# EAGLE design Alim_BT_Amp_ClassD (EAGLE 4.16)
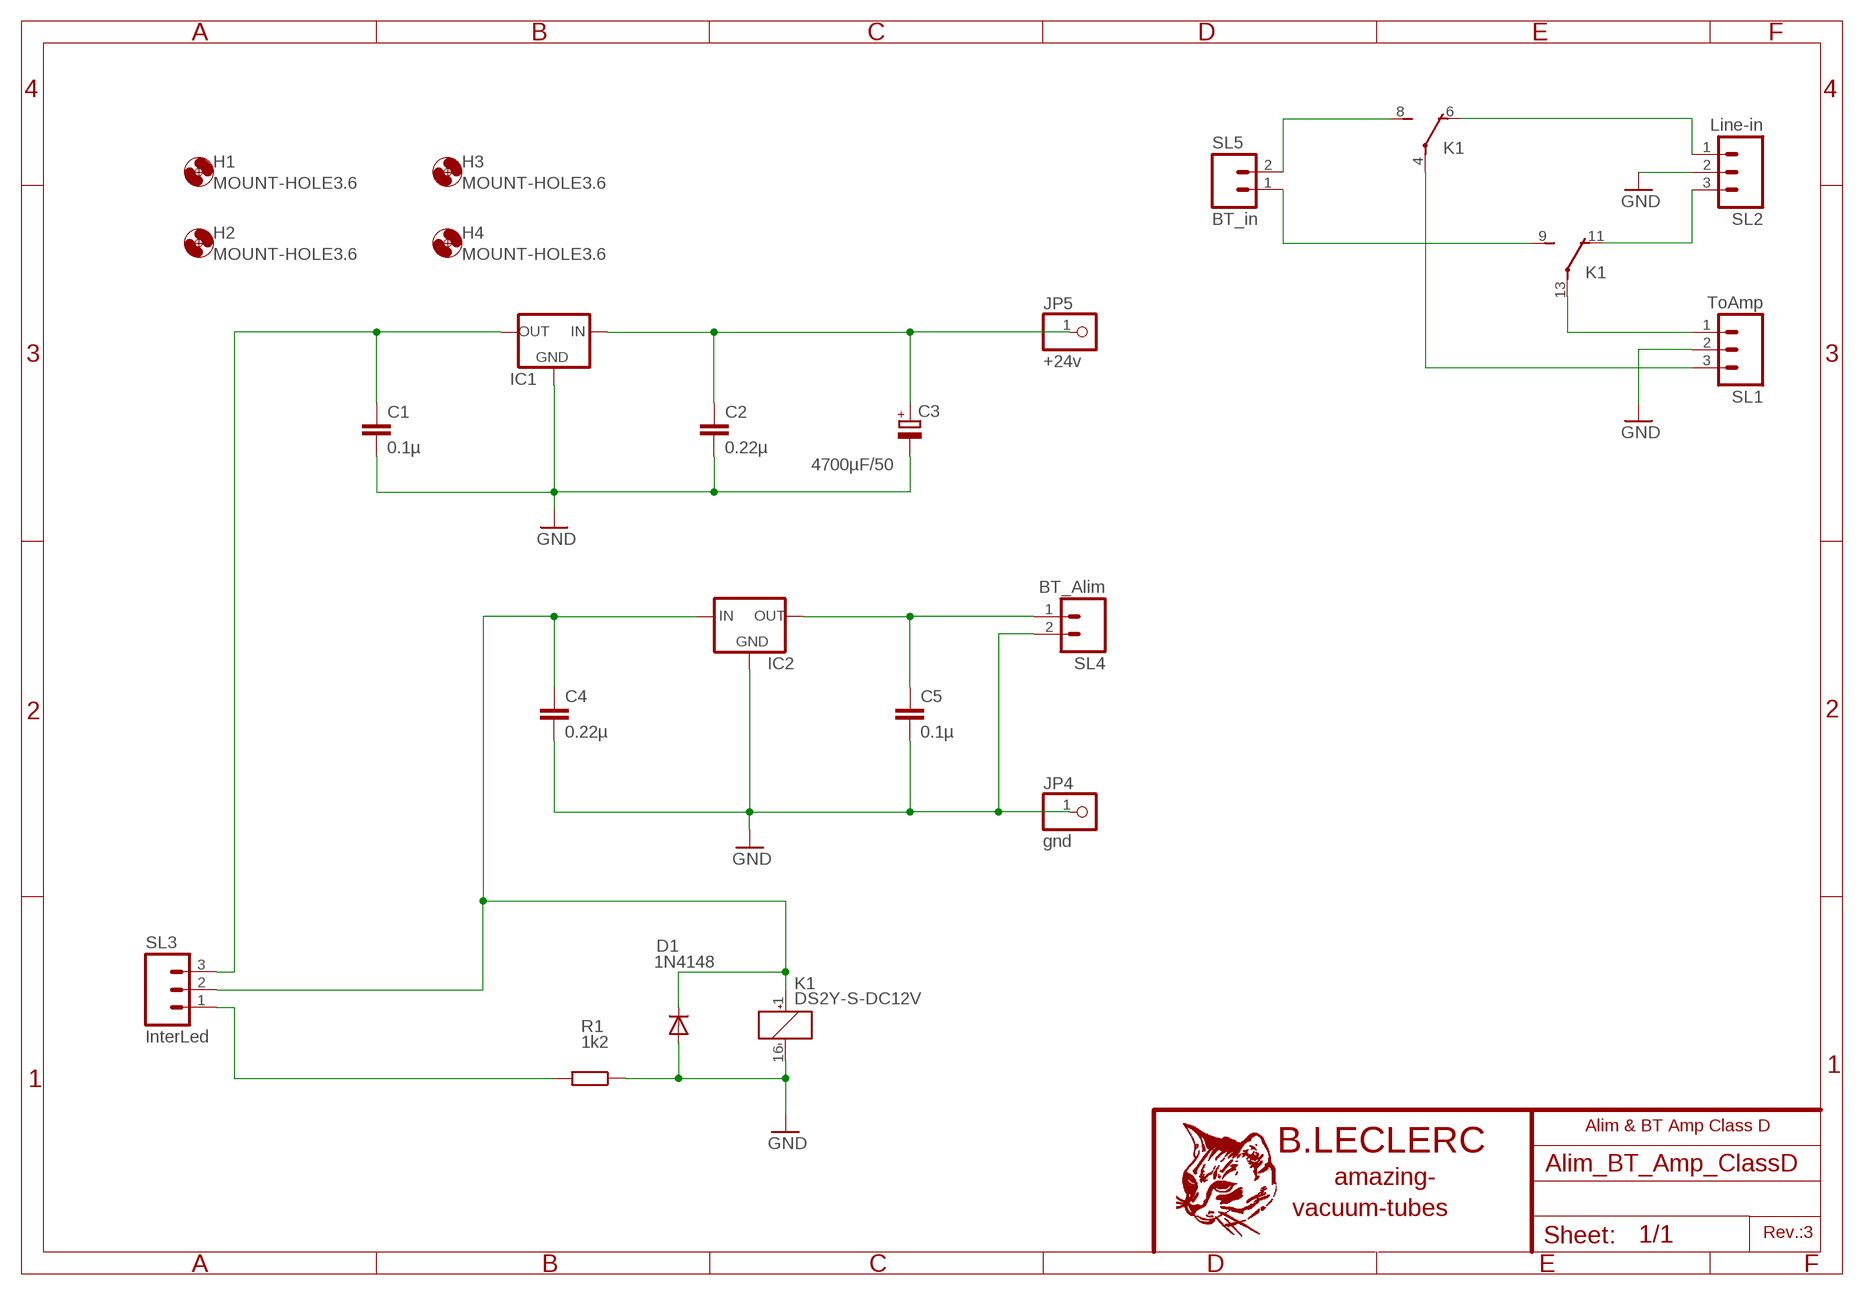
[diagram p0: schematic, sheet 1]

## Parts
C1  0.1µ  C-EU102-064X133  [C102-064X133]
C2  0.22µ  C-EU102-064X133  [C102-064X133]
C3  4700µF/50  CPOL-EUE7.5-18  [E7,5-18]
C4  0.22µ  C-EU102-064X133  [C102-064X133]
C5  0.1µ  C-EU102-064X133  [C102-064X133]
D1  1N4148  [DO35-10]
H1  MOUNT-HOLE3.6  [3,6]
H2  MOUNT-HOLE3.6  [3,6]
H3  MOUNT-HOLE3.6  [3,6]
H4  MOUNT-HOLE3.6  [3,6]
IC1  78XXL  [78XXL]
IC2  78XXL  [78XXL]
JP4  gnd  PINHD-1X1  [1X01]
JP5  +24v  PINHD-1X1  [1X01]
K1  DS2Y-S-DC12V  DS2Y-S-DC24V  [DS2Y]
R1  1k2  R-EU_0207/12  [0207/12]
SL1  ToAmp  M03  [03P]
SL2  Line-in  M03  [03P]
SL3  InterLed  M03  [03P]
SL4  BT_Alim  M02  [02P]
SL5  BT_in  M02  [02P]

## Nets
GND: C1.2 C2.2 C3.- C4.2 C5.2 D1.A IC1.GND IC2.GND JP4.1 K1.16(1:-) R1.1 SL1.2 SL2.2 SL4.2
N$1: K1.4(2:P) SL1.3
N$2: R1.2 SL3.1
N$4: C4.1 D1.C IC2.IN K1.1(1:+) SL3.2
N$5: K1.8(2:S) SL5.2
N$6: C5.1 IC2.OUT SL4.1
N$7: K1.6(2:O) SL2.1
N$8: C1.1 IC1.OUT SL3.3
N$9: K1.9(3:S) SL5.1
N$10: K1.11(3:O) SL2.3
N$11: K1.13(3:P) SL1.1
N$13: C2.1 C3.+ IC1.IN JP5.1

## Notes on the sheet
- Alim & BT Amp Class D
- Rev.:3

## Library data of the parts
C1 C2 C4 C5 = rcl:C-EU: CAPACITOR, European symbol
C3 = rcl:CPOL-EU: POLARIZED CAPACITOR, European symbol
D1 = diode:1N4148: DIODE
H1-H4 = holes:MOUNT-HOLE: MOUNTING HOLE with drill center marker
IC1 IC2 = v-reg:78XXL: VOLTAGE REGULATOR
JP4 JP5 = pinhead:PINHD-1X1: PIN HEADER
K1 = relay:DS2Y-S-DC*: MINIATURE RELAY NAiS Source: http://www.mew-europe.com/.. en_ds_61005_0023.pdf
R1 = rcl:R-EU_: RESISTOR, European symbol
SL1-SL3 = con-amp-quick:M03: AMP QUICK CONNECTOR
SL4 SL5 = con-amp-quick:M02: AMP QUICK CONNECTOR

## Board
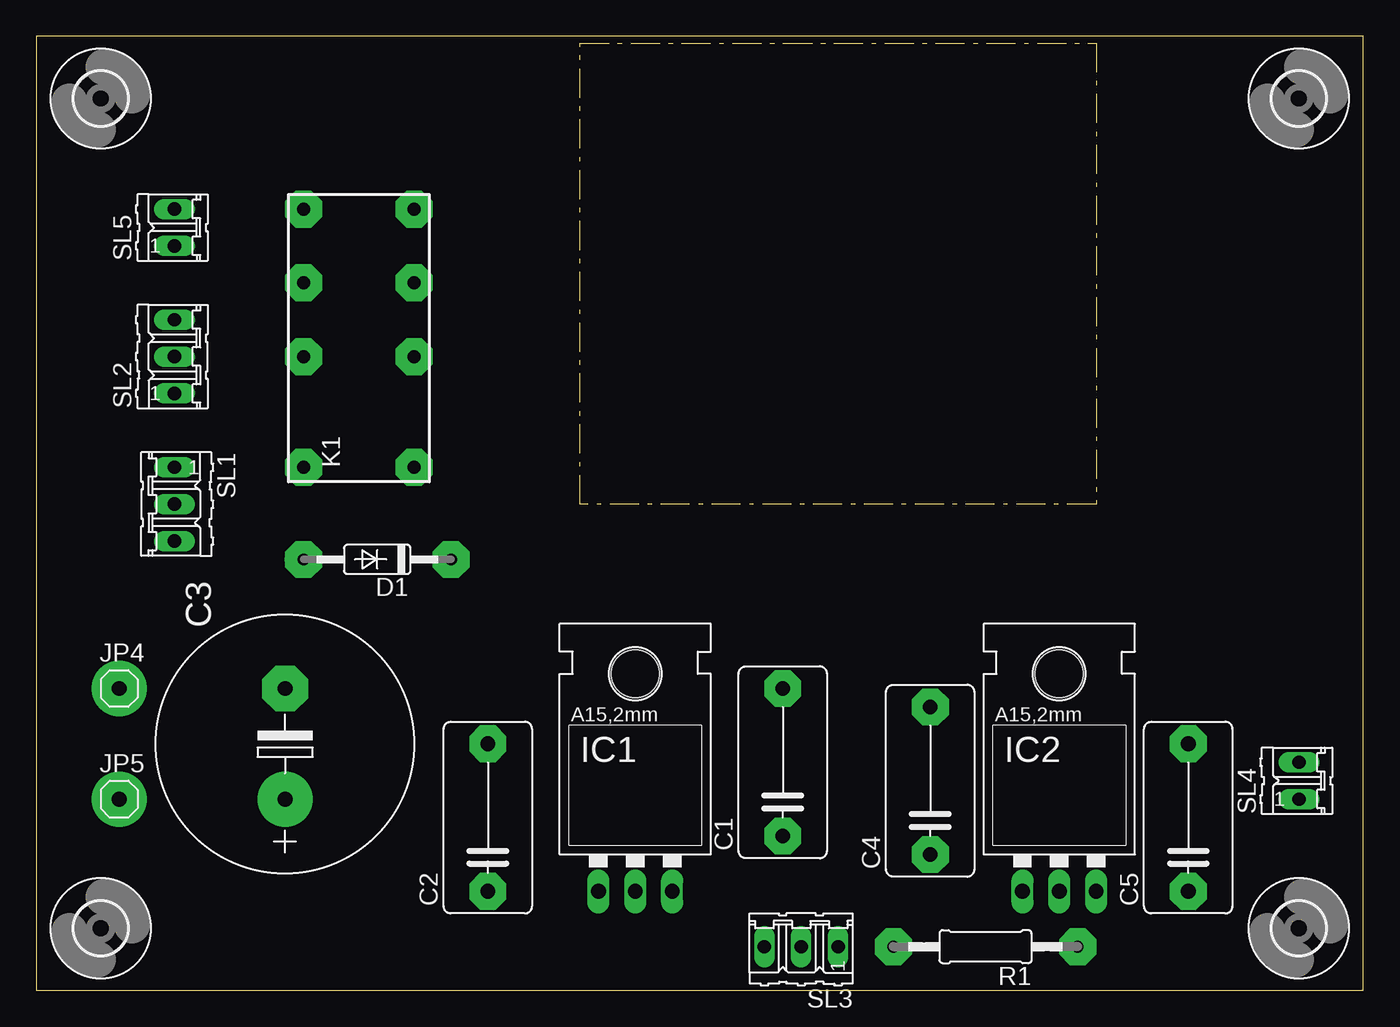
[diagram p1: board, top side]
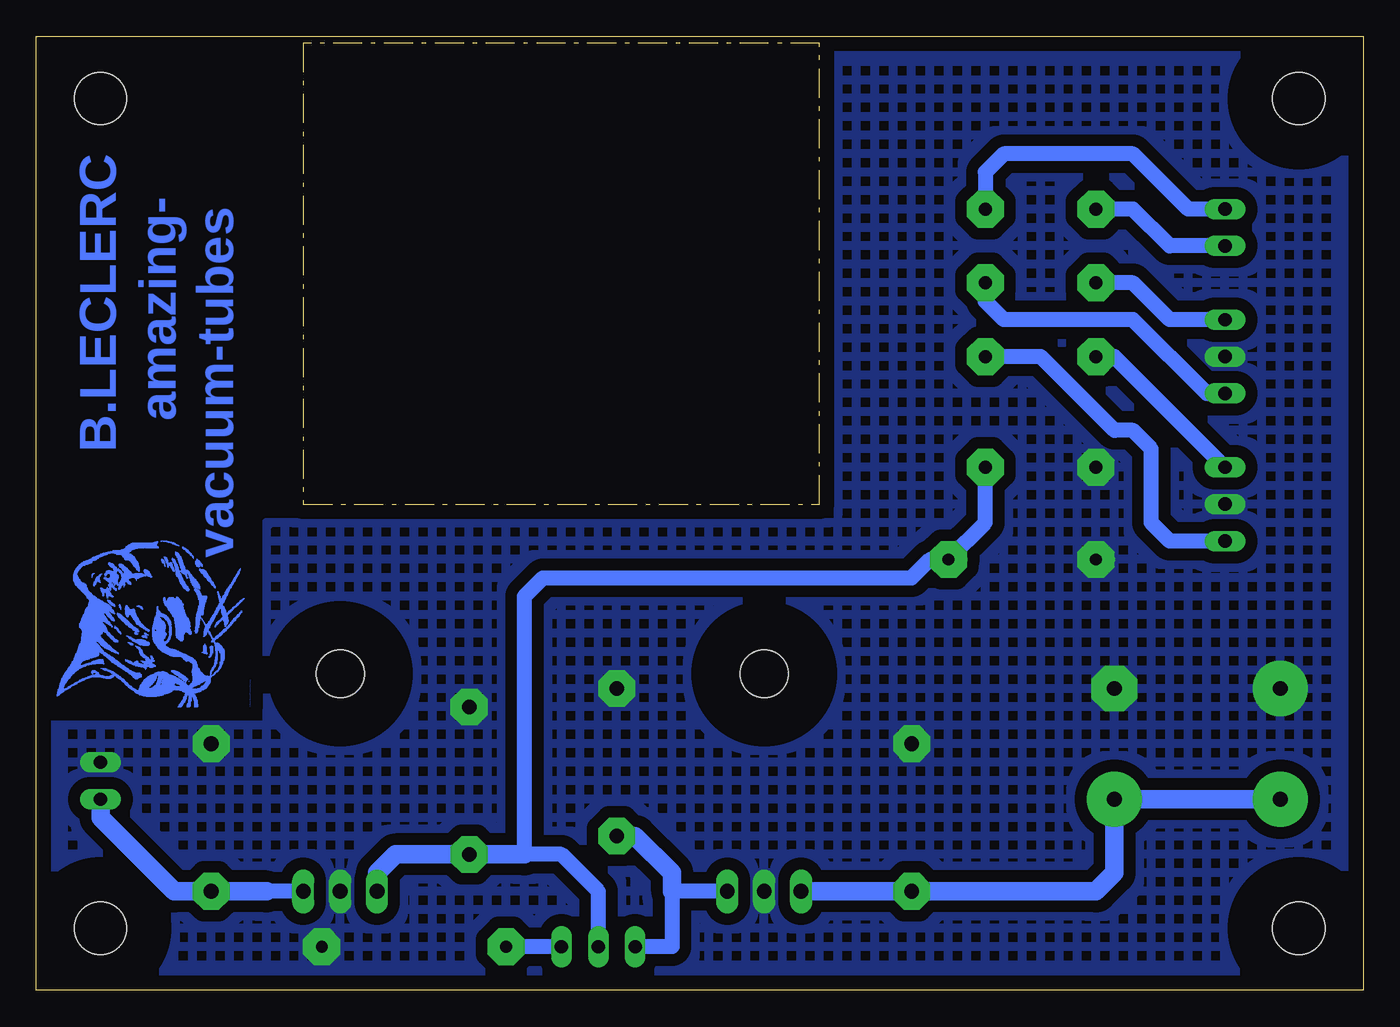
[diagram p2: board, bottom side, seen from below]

Size 91.42 x 65.71 mm. Coordinates in mm from the lower left corner, seen from the top.
Outline: 0,0 91.42,0 91.42,65.71 0,65.71 0,0
Outline: 37.46,65.24 73.02,65.24 73.02,33.49 37.46,33.49 37.46,65.24
Copper layers (1*16): Top 0.035mm / dielectric 1.5mm / Bottom 0.035mm
Design rules "default": minimum track width 10mil, minimum drill 24mil, track to track 8mil, track to pad 8mil, pad to pad 8mil, via to via 8mil, smd to smd 8mil, copper to edge 40mil, drill to drill 8mil, minimum pad ring 10mil, minimum via ring 8mil, stop-mask expansion 4mil, vias tented up to drill 0mil, thermal gap 10mil

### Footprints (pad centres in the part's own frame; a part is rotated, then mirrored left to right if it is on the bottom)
C102-064X133 = drill 1.016 octagon: 1 -5.08,0; 2 5.08,0
E7,5-18 = drill 1.016 pad 3.15 round: + -3.81,0 | drill 1.016 pad 3.15 octagon: - 3.81,0
DO35-10 = drill 0.813 long: A 5.08,0; C -5.08,0
3,6 = hole 3.6: 0,0
78XXL = drill 1.016 long: GND 0,-3.81; IN -2.54,-3.81; OUT 2.54,-3.81 | hole 3.302: 0,11.176
1X01 = drill 1.016 octagon: 1 0,0
DS2Y = drill 0.9 round: 1 -8.89,-3.81; 4 -1.27,-3.81; 6 3.81,-3.81; 8 8.89,-3.81; 9 8.89,3.81; 11 3.81,3.81; 13 -1.27,3.81; 16 -8.89,3.81
0207/12 = drill 0.813 octagon: 1 -6.35,0; 2 6.35,0
03P = drill 0.914 long: 1 -2.54,0; 2 0,0; 3 2.54,0
02P = drill 0.914 long: 1 -1.27,0; 2 1.27,0

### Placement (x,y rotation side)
C1  51.43,15.71 90 top
C2  31.11,11.9 90 top
C3  17.14,16.98 90 top
C4  61.59,14.44 90 top
C5  79.37,11.9 90 top
D1  23.49,29.68 180 top
H1  86.99,4.28 0 top
H2  86.99,61.43 0 top
H3  4.44,61.43 0 top
H4  4.44,4.28 0 top
IC1  41.27,10.63 0 top
IC2  70.48,10.63 0 top
JP4  5.71,20.79 0 top
JP5  5.71,13.17 0 top
K1  22.22,44.92 90 top
R1  65.4,3.01 180 top
SL1  9.52,33.49 270 top
SL2  9.52,43.65 90 top
SL3  52.7,3.01 180 top
SL4  86.99,14.44 90 top
SL5  9.52,52.54 90 top
U$2  [CHAT1]  76.83,19.52 90 bottom

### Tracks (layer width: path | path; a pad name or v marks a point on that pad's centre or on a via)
GND  (via drill 0.5 pad 1.27, 0.5 pad 2.54, 0.5 pad 3.81)
  other vias: 9.52,43.65 9.52,33.49 18.41,36.03 18.41,29.68 5.71,20.79 71.75,3.01 41.27,6.82 70.48,6.82 31.11,16.98 51.43,20.79 61.59,19.52 79.37,16.98 86.99,15.71
  pour Bottom (isolate 0.813, no thermals, hatched): 0.63,65.24 36.19,65.24 36.19,32.22 75.56,32.22 75.56,18.25 90.8,18.25 90.8,0.47 0.63,0.47
N$1
  Bottom 1.016: SL1.3 13.33,30.95 14.6,32.22 14.6,37.3 15.87,38.57 17.14,38.57 22.22,43.65 K1.4
N$2
  Bottom 1.016: SL3.1 R1.2
N$3  (via drill 0.5 pad 1.27)
  other vias: 9.52,53.81
N$4
  Bottom 1.016: K1.1 26.03,32.22 D1.C 29.84,29.68 31.11,28.41 56.51,28.41 57.78,27.14 57.78,9.36 55.24,9.36 52.7,6.82 SL3.2 | 67.94,8.09 IC2.IN
  Bottom 1.27: 57.78,9.36 C4.1 66.67,9.36 67.94,8.09
N$5
  Bottom 1.016: SL5.2 12.06,53.81 15.87,57.62 24.76,57.62 26.03,56.35 K1.8
N$6
  Bottom 1.016: IC2.OUT 75.56,6.82
  Bottom 1.27: 75.56,6.82 C5.1 81.91,6.82 86.99,11.9 SL4.1
N$7
  Bottom 1.016: SL2.1 10.79,41.11 15.87,46.19 24.76,46.19 26.03,47.46 K1.6
N$8
  Bottom 1.016: IC1.OUT 47.62,6.82 47.62,3.01 SL3.3
  Bottom 1.27: C1.1 50.16,10.63 47.62,8.09 47.62,6.82
N$9
  Bottom 1.016: SL5.1 13.33,51.27 15.87,53.81 K1.9
N$10
  Bottom 1.016: SL2.3 13.33,46.19 15.87,48.73 K1.11
N$11
  Bottom 1.016: SL1.1 17.14,43.65 K1.13
N$12  (via drill 0.5 pad 1.27)
  other vias: 9.52,51.27
N$13
  Bottom 1.27: JP5.1 C3.+ 17.14,8.09 18.41,6.82 C2.1 IC1.IN
N$14  (via drill 0.5 pad 1.27)
  other vias: 9.52,46.19
N$16  (via drill 0.5 pad 1.27)
  other vias: 9.52,41.11
N$17  (via drill 0.5 pad 1.27)
  other vias: 9.52,36.03
N$18  (via drill 0.5 pad 1.27)
  other vias: 38.73,6.82
N$19  (via drill 0.5 pad 1.27)
  other vias: 9.52,30.95
N$20  (via drill 0.5 pad 1.27)
  other vias: 50.16,3.01
N$21  (via drill 0.5 pad 1.27)
  other vias: 52.7,3.01
N$22  (via drill 0.5 pad 1.27)
  other vias: 55.24,3.01
N$24  (via drill 0.5 pad 1.27)
  other vias: 43.81,6.82
N$25  (via drill 0.5 pad 3.81)
  other vias: 5.71,13.17
N$26  (via drill 0.5 pad 1.27)
  other vias: 86.99,13.17
N$27  (via drill 0.5 pad 3.81)
  other vias: 17.14,13.17
N$28  (via drill 0.5 pad 2.54)
  other vias: 18.41,53.81
N$29  (via drill 0.5 pad 2.54)
  other vias: 26.03,53.81
N$30  (via drill 0.5 pad 2.54)
  other vias: 26.03,48.73
N$31  (via drill 0.5 pad 2.54)
  other vias: 26.03,43.65
N$32  (via drill 0.5 pad 2.54)
  other vias: 26.03,36.03
N$33  (via drill 0.5 pad 1.27)
  other vias: 67.94,6.82
N$34  (via drill 0.5 pad 2.54)
  other vias: 18.41,43.65
N$35  (via drill 0.5 pad 2.54)
  other vias: 18.41,48.73
N$36  (via drill 0.5 pad 2.54)
  other vias: 28.57,29.68
N$38  (via drill 0.5 pad 2.54)
  other vias: 59.05,3.01
N$39  (via drill 0.5 pad 1.27)
  other vias: 73.02,6.82
N$42  (via drill 0.5 pad 2.54)
  other vias: 31.11,6.82
N$43  (via drill 0.5 pad 2.54)
  other vias: 61.59,9.36
N$46  (via drill 0.5 pad 2.54)
  other vias: 51.43,10.63
N$47  (via drill 0.5 pad 2.54)
  other vias: 79.37,6.82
